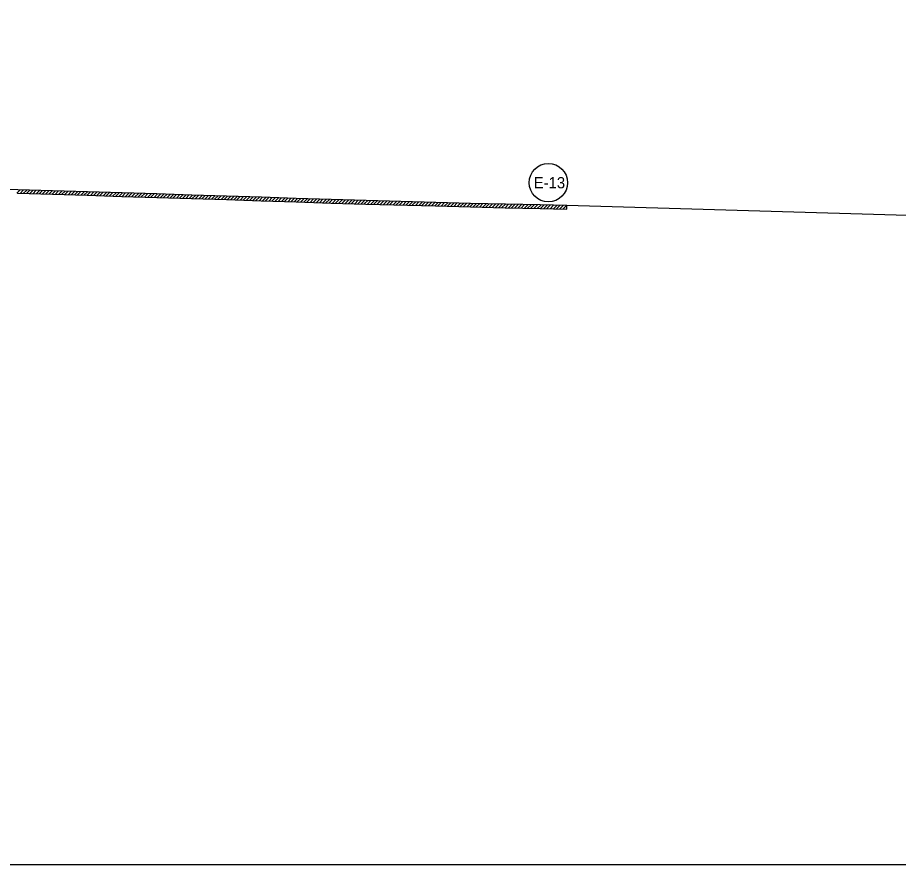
# Model space of a CAD drawing. Extents: x 976877 to 983987, y 1525984 to 1526526.
# Drawn here: x 982583.2 to 982962.3, y 1526043.8 to 1526408 of the extents above; entities that cross this region are included whole.
import ezdxf

# ---------------------------------------------------------------- set-up
doc = ezdxf.new("R2010")
doc.units = 0
doc.layers.add('R_Erosion', color=7, linetype='Continuous')
doc.layers.add('R_No Plot', color=7, linetype='Continuous')

msp = doc.modelspace()

# ---------------------------------------------------------------- linework, layer by layer
at = {"layer": 'R_Erosion'}
for p, q in [((982582.85, 1526332.43), (982584.31, 1526333.89)), ((982584.23, 1526332.39), (982585.69, 1526333.85)), ((982585.6, 1526332.36), (982587.06, 1526333.82)), ((982586.98, 1526332.32), (982588.44, 1526333.78)), ((982588.35, 1526332.28), (982589.81, 1526333.74)), ((982589.73, 1526332.24), (982591.19, 1526333.7)), ((982591.11, 1526332.2), (982592.57, 1526333.66)), ((982592.48, 1526332.17), (982593.94, 1526333.63)), ((982593.86, 1526332.13), (982595.32, 1526333.59)), ((982595.23, 1526332.09), (982596.69, 1526333.55)), ((982596.61, 1526332.05), (982598.07, 1526333.51)), ((982597.99, 1526332.01), (982599.44, 1526333.47)), ((982613.19, 1526333.07), (982598.2, 1526333.51)), ((982613.19, 1526333.07), (982598.2, 1526333.51)), ((982599.36, 1526331.97), (982600.82, 1526333.43)), ((982600.74, 1526331.93), (982602.19, 1526333.39)), ((982602.11, 1526331.89), (982603.57, 1526333.35)), ((982603.48, 1526331.85), (982604.94, 1526333.31)), ((982604.86, 1526331.81), (982606.32, 1526333.27)), ((982606.23, 1526331.77), (982607.69, 1526333.23)), ((982607.61, 1526331.73), (982609.06, 1526333.19)), ((982608.98, 1526331.69), (982610.44, 1526333.15)), ((982610.35, 1526331.65), (982611.81, 1526333.11)), ((982611.73, 1526331.61), (982613.19, 1526333.07)), ((982613.1, 1526331.57), (982614.56, 1526333.03)), ((982614.47, 1526331.53), (982615.93, 1526332.98)), ((982615.84, 1526331.49), (982617.3, 1526332.94)), ((982617.22, 1526331.44), (982618.67, 1526332.9)), ((982618.59, 1526331.4), (982620.04, 1526332.85)), ((982619.96, 1526331.36), (982621.41, 1526332.81)), ((982621.33, 1526331.31), (982622.78, 1526332.77)), ((982622.7, 1526331.27), (982624.15, 1526332.72)), ((982624.07, 1526331.23), (982625.53, 1526332.68)), ((982625.44, 1526331.18), (982626.9, 1526332.64)), ((982626.81, 1526331.14), (982628.27, 1526332.6)), ((982628.18, 1526331.1), (982629.64, 1526332.55)), ((982629.56, 1526331.06), (982631.01, 1526332.51)), ((982630.93, 1526331.01), (982632.38, 1526332.47)), ((982632.3, 1526330.97), (982633.75, 1526332.43)), ((982633.67, 1526330.93), (982635.13, 1526332.38)), ((982635.04, 1526330.89), (982636.5, 1526332.34)), ((982636.41, 1526330.84), (982637.87, 1526332.3)), ((982637.79, 1526330.8), (982639.24, 1526332.26)), ((982639.16, 1526330.76), (982640.61, 1526332.21)), ((982640.53, 1526330.72), (982641.99, 1526332.17)), ((982641.9, 1526330.67), (982643.36, 1526332.13)), ((982643.27, 1526330.63), (982644.73, 1526332.09)), ((982644.64, 1526330.59), (982646.1, 1526332.04)), ((982646.02, 1526330.54), (982647.47, 1526332)), ((982647.39, 1526330.5), (982648.84, 1526331.96)), ((982648.76, 1526330.46), (982650.21, 1526331.91)), ((982650.13, 1526330.42), (982651.58, 1526331.87)), ((982651.5, 1526330.37), (982652.96, 1526331.83)), ((982652.87, 1526330.33), (982654.33, 1526331.78)), ((982654.24, 1526330.29), (982655.7, 1526331.74)), ((982655.61, 1526330.24), (982657.07, 1526331.7)), ((982656.98, 1526330.2), (982658.44, 1526331.66)), ((982658.36, 1526330.16), (982659.81, 1526331.61)), ((982659.73, 1526330.12), (982661.19, 1526331.57)), ((982661.1, 1526330.07), (982662.56, 1526331.53)), ((982662.48, 1526330.03), (982663.93, 1526331.49)), ((982663.85, 1526329.99), (982665.31, 1526331.45)), ((982665.22, 1526329.95), (982666.68, 1526331.41)), ((982666.59, 1526329.91), (982668.05, 1526331.37)), ((982667.97, 1526329.87), (982669.42, 1526331.33)), ((982669.34, 1526329.83), (982670.8, 1526331.29)), ((982670.71, 1526329.79), (982672.17, 1526331.24)), ((982672.09, 1526329.75), (982673.54, 1526331.2)), ((982688.09, 1526330.7), (982673.11, 1526331.22)), ((982688.09, 1526330.7), (982673.11, 1526331.22)), ((982673.46, 1526329.7), (982674.91, 1526331.15)), ((982674.83, 1526329.66), (982676.28, 1526331.11)), ((982676.19, 1526329.61), (982677.64, 1526331.06)), ((982677.56, 1526329.56), (982679.01, 1526331.01)), ((982678.93, 1526329.52), (982680.38, 1526330.97)), ((982680.3, 1526329.47), (982681.75, 1526330.92)), ((982681.66, 1526329.42), (982683.11, 1526330.87)), ((982683.03, 1526329.38), (982684.48, 1526330.83)), ((982684.4, 1526329.33), (982685.85, 1526330.78)), ((982685.77, 1526329.28), (982687.22, 1526330.73)), ((982687.13, 1526329.24), (982688.58, 1526330.69)), ((982688.5, 1526329.19), (982689.95, 1526330.64)), ((982689.87, 1526329.14), (982691.32, 1526330.59)), ((982691.24, 1526329.1), (982692.69, 1526330.55)), ((982692.6, 1526329.05), (982694.05, 1526330.5)), ((982693.97, 1526329), (982695.42, 1526330.45)), ((982695.34, 1526328.96), (982696.79, 1526330.41)), ((982696.71, 1526328.91), (982698.16, 1526330.36)), ((982698.07, 1526328.86), (982699.52, 1526330.31)), ((982699.44, 1526328.81), (982700.89, 1526330.27)), ((982700.81, 1526328.77), (982702.26, 1526330.22)), ((982702.18, 1526328.72), (982703.63, 1526330.17)), ((982703.04, 1526328.69), (982718.1, 1526328.23)), ((982703.04, 1526328.69), (982718.1, 1526328.23)), ((982703.04, 1526328.69), (982718.1, 1526328.23)), ((982703.54, 1526328.68), (982705, 1526330.13)), ((982704.92, 1526328.63), (982706.37, 1526330.09)), ((982706.29, 1526328.59), (982707.75, 1526330.05)), ((982707.66, 1526328.55), (982709.12, 1526330.01)), ((982709.03, 1526328.51), (982710.49, 1526329.97)), ((982710.41, 1526328.47), (982711.86, 1526329.92)), ((982711.78, 1526328.43), (982713.23, 1526329.88)), ((982713.15, 1526328.38), (982714.61, 1526329.84)), ((982714.52, 1526328.34), (982715.98, 1526329.8)), ((982715.9, 1526328.3), (982717.35, 1526329.76)), ((982717.27, 1526328.26), (982718.73, 1526329.72)), ((982718.1, 1526328.23), (982733.1, 1526327.81)), ((982718.1, 1526328.23), (982733.1, 1526327.81)), ((982718.1, 1526328.23), (982733.1, 1526327.81)), ((982718.64, 1526328.22), (982720.1, 1526329.68)), ((982720.02, 1526328.18), (982721.48, 1526329.64)), ((982721.39, 1526328.14), (982722.85, 1526329.6)), ((982722.77, 1526328.1), (982724.23, 1526329.56)), ((982724.14, 1526328.06), (982725.6, 1526329.52)), ((982725.52, 1526328.03), (982726.98, 1526329.49)), ((982726.9, 1526327.99), (982728.36, 1526329.45)), ((982728.27, 1526327.95), (982729.73, 1526329.41)), ((982729.65, 1526327.91), (982731.11, 1526329.37)), ((982731.02, 1526327.87), (982732.48, 1526329.33)), ((982732.4, 1526327.83), (982733.86, 1526329.29)), ((982733.1, 1526327.81), (982763.09, 1526327)), ((982733.1, 1526327.81), (982763.09, 1526327)), ((982733.1, 1526327.81), (982763.09, 1526327)), ((982733.78, 1526327.8), (982735.24, 1526329.26)), ((982735.15, 1526327.76), (982736.61, 1526329.22)), ((982736.53, 1526327.72), (982737.99, 1526329.18)), ((982737.91, 1526327.68), (982739.37, 1526329.14)), ((982739.28, 1526327.64), (982740.74, 1526329.11)), ((982740.66, 1526327.61), (982742.12, 1526329.07)), ((982742.04, 1526327.57), (982743.5, 1526329.03)), ((982743.41, 1526327.53), (982744.87, 1526328.99)), ((982744.79, 1526327.49), (982746.25, 1526328.96)), ((982746.17, 1526327.46), (982747.63, 1526328.92)), ((982747.54, 1526327.42), (982749, 1526328.88)), ((982748.92, 1526327.38), (982750.38, 1526328.84)), ((982750.3, 1526327.34), (982751.76, 1526328.81)), ((982751.67, 1526327.31), (982753.13, 1526328.77)), ((982753.05, 1526327.27), (982754.51, 1526328.73)), ((982754.43, 1526327.23), (982755.89, 1526328.69)), ((982755.8, 1526327.19), (982757.26, 1526328.65)), ((982757.18, 1526327.16), (982758.64, 1526328.62)), ((982758.56, 1526327.12), (982760.02, 1526328.58)), ((982759.93, 1526327.08), (982761.39, 1526328.54)), ((982761.31, 1526327.04), (982762.77, 1526328.5)), ((982762.69, 1526327.01), (982764.15, 1526328.47)), ((982764.06, 1526326.97), (982765.52, 1526328.43)), ((982765.44, 1526326.93), (982766.9, 1526328.39)), ((982766.82, 1526326.9), (982768.28, 1526328.36)), ((982768.19, 1526326.86), (982769.66, 1526328.32)), ((982769.57, 1526326.82), (982771.03, 1526328.28)), ((982770.95, 1526326.78), (982772.41, 1526328.25)), ((982772.33, 1526326.75), (982773.79, 1526328.21)), ((982773.7, 1526326.71), (982775.17, 1526328.17)), ((982775.08, 1526326.67), (982776.54, 1526328.14)), ((982776.46, 1526326.64), (982777.92, 1526328.1)), ((982777.84, 1526326.6), (982779.3, 1526328.06)), ((982779.22, 1526326.57), (982780.68, 1526328.03)), ((982780.6, 1526326.53), (982782.06, 1526328)), ((982781.98, 1526326.5), (982783.44, 1526327.96)), ((982783.35, 1526326.46), (982784.82, 1526327.93)), ((982784.73, 1526326.43), (982786.2, 1526327.89)), ((982786.11, 1526326.39), (982787.58, 1526327.86)), ((982787.49, 1526326.36), (982788.96, 1526327.82)), ((982788.87, 1526326.33), (982790.34, 1526327.79)), ((982790.25, 1526326.29), (982791.72, 1526327.76)), ((982791.63, 1526326.26), (982793.1, 1526327.72)), ((982793.01, 1526326.22), (982794.48, 1526327.69)), ((982794.4, 1526326.19), (982795.87, 1526327.66)), ((982795.78, 1526326.16), (982797.25, 1526327.63)), ((982797.17, 1526326.13), (982798.63, 1526327.6)), ((982798.55, 1526326.1), (982800.02, 1526327.57)), ((982799.93, 1526326.07), (982801.4, 1526327.54)), ((982801.32, 1526326.04), (982802.78, 1526327.51)), ((982802.7, 1526326.01), (982804.17, 1526327.48)), ((982804.08, 1526325.98), (982805.55, 1526327.45)), ((982805.47, 1526325.95), (982806.93, 1526327.42)), ((982806.85, 1526325.92), (982808.32, 1526327.38)), ((982819.58, 1526327.12), (982808.11, 1526327.39)), ((982819.58, 1526327.12), (982808.11, 1526327.39)), ((982808.23, 1526325.89), (982809.7, 1526327.35)), ((982809.62, 1526325.85), (982811.08, 1526327.32)), ((982811, 1526325.82), (982812.46, 1526327.29)), ((982812.38, 1526325.79), (982813.84, 1526327.25)), ((982813.76, 1526325.75), (982815.22, 1526327.22)), ((982815.14, 1526325.72), (982816.61, 1526327.19)), ((982816.52, 1526325.69), (982817.99, 1526327.15)), ((982763.09, 1526327), (982778.08, 1526326.59)), ((982763.09, 1526327), (982778.08, 1526326.59)), ((982763.09, 1526327), (982778.08, 1526326.59)), ((982778.08, 1526326.59), (982793.08, 1526326.22)), ((982778.08, 1526326.59), (982793.08, 1526326.22)), ((982778.08, 1526326.59), (982793.08, 1526326.22)), ((982817.9, 1526325.66), (982819.37, 1526327.12)), ((982819.28, 1526325.62), (982819.55, 1526325.89)), ((982819.55, 1526325.62), (982819.58, 1526327.12)), ((982819.55, 1526325.62), (982819.58, 1526327.12))]:
    msp.add_line(p, q, dxfattribs=at)
for points in [[(982598.19, 1526333.51), (982583.2, 1526333.92), (982568.21, 1526334.34)], [(982598.19, 1526333.51), (982583.2, 1526333.92), (982568.21, 1526334.34)], [(982583.16, 1526332.42), (982598.15, 1526332.01), (982613.14, 1526331.57), (982628.08, 1526331.1)], [(982583.16, 1526332.42), (982598.15, 1526332.01), (982613.14, 1526331.57), (982628.08, 1526331.1)], [(982583.16, 1526332.42), (982598.15, 1526332.01), (982613.14, 1526331.57), (982628.08, 1526331.1)], [(982643.12, 1526332.14), (982628.12, 1526332.6), (982613.19, 1526333.07)], [(982643.12, 1526332.14), (982628.12, 1526332.6), (982613.19, 1526333.07)], [(982628.08, 1526331.1), (982643.07, 1526330.64), (982658.06, 1526330.17)], [(982628.08, 1526331.1), (982643.07, 1526330.64), (982658.06, 1526330.17)], [(982628.08, 1526331.1), (982643.07, 1526330.64), (982658.06, 1526330.17)], [(982673.1, 1526331.22), (982658.11, 1526331.66), (982643.12, 1526332.14)], [(982673.1, 1526331.22), (982658.11, 1526331.66), (982643.12, 1526332.14)], [(982658.07, 1526330.17), (982673.05, 1526329.72), (982688.04, 1526329.2), (982703.03, 1526328.69)], [(982658.07, 1526330.17), (982673.05, 1526329.72), (982688.04, 1526329.2), (982703.03, 1526328.69)], [(982658.07, 1526330.17), (982673.05, 1526329.72), (982688.04, 1526329.2), (982703.03, 1526328.69)], [(982808.11, 1526327.39), (982793.12, 1526327.72), (982778.12, 1526328.09), (982763.13, 1526328.49), (982733.14, 1526329.31), (982718.14, 1526329.73), (982703.09, 1526330.19), (982688.09, 1526330.7)], [(982808.11, 1526327.39), (982793.12, 1526327.72), (982778.12, 1526328.09), (982763.13, 1526328.49), (982733.14, 1526329.31), (982718.14, 1526329.73), (982703.09, 1526330.19), (982688.09, 1526330.7)], [(982793.08, 1526326.22), (982808.08, 1526325.89), (982819.55, 1526325.62)], [(982793.08, 1526326.22), (982808.08, 1526325.89), (982819.55, 1526325.62)], [(982793.08, 1526326.22), (982808.08, 1526325.89), (982819.55, 1526325.62)]]:
    msp.add_lwpolyline(points, dxfattribs=at)
msp.add_circle((982811.62, 1526336.98), 8.26, dxfattribs=at)
for centre, start, end in [((982583.2, 1526333.92), 268.4108, 268.4146), ((982598.15, 1526332.01), 88.3268, 88.4146), ((982613.14, 1526331.57), 88.1975, 88.3268), ((982613.14, 1526331.57), 88.1975, 88.3268), ((982628.12, 1526332.6), 268.1975, 268.2312), ((982643.07, 1526330.64), 88.1968, 88.2312), ((982643.07, 1526330.64), 88.1968, 88.2312), ((982673.05, 1526329.72), 88.0439, 88.2847), ((982673.05, 1526329.72), 88.0439, 88.2847), ((982658.11, 1526331.66), 268.1968, 268.2847), ((982688.04, 1526329.2), 88.0402, 88.0439), ((982703.09, 1526330.19), 268.0402, 268.2539), ((982703.09, 1526330.19), 268.0402, 268.2539), ((982703.09, 1526330.19), 268.0402, 268.2539), ((982718.14, 1526329.73), 268.2539, 268.3993), ((982718.14, 1526329.73), 268.2539, 268.3993), ((982733.14, 1526329.31), 268.3993, 268.4375), ((982808.08, 1526325.89), 88.6364, 88.7318), ((982808.08, 1526325.89), 88.6364, 88.7318), ((982763.13, 1526328.49), 268.4375, 268.4643), ((982778.12, 1526328.09), 268.4643, 268.5789), ((982778.12, 1526328.09), 268.4643, 268.5789), ((982793.12, 1526327.72), 268.5789, 268.7318), ((982793.12, 1526327.72), 268.5789, 268.7318), ((982793.12, 1526327.72), 268.5789, 268.7318)]:
    msp.add_arc(centre, 1.5, start, end, dxfattribs=at)
at = {"layer": 'R_No Plot'}
msp.add_line((982980.66, 1526322.43), (982819.58, 1526327.12), dxfattribs=at)
for points in [[(980311.86, 1526407.98), (980311.86, 1526043.76), (983987.45, 1526043.76), (983987.45, 1526292.17)], [(982819.58, 1526327.12), (982808.11, 1526327.39), (982793.12, 1526327.72), (982778.12, 1526328.09), (982763.13, 1526328.49), (982733.14, 1526329.31), (982718.14, 1526329.73), (982703.09, 1526330.19), (982688.09, 1526330.7), (982673.1, 1526331.22), (982658.11, 1526331.66), (982643.12, 1526332.14), (982628.12, 1526332.6), (982613.19, 1526333.07), (982598.19, 1526333.51), (982583.2, 1526333.92), (982568.21, 1526334.34)]]:
    msp.add_lwpolyline(points, dxfattribs=at)

# ---------------------------------------------------------------- texts
at = {"layer": 'R_Erosion'}
msp.add_text('E-13', height=4.8, dxfattribs=at).set_placement((982805.29, 1526334.58))

doc.saveas('drawing.dxf')
